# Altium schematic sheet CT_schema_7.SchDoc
size 405 x 220 mm
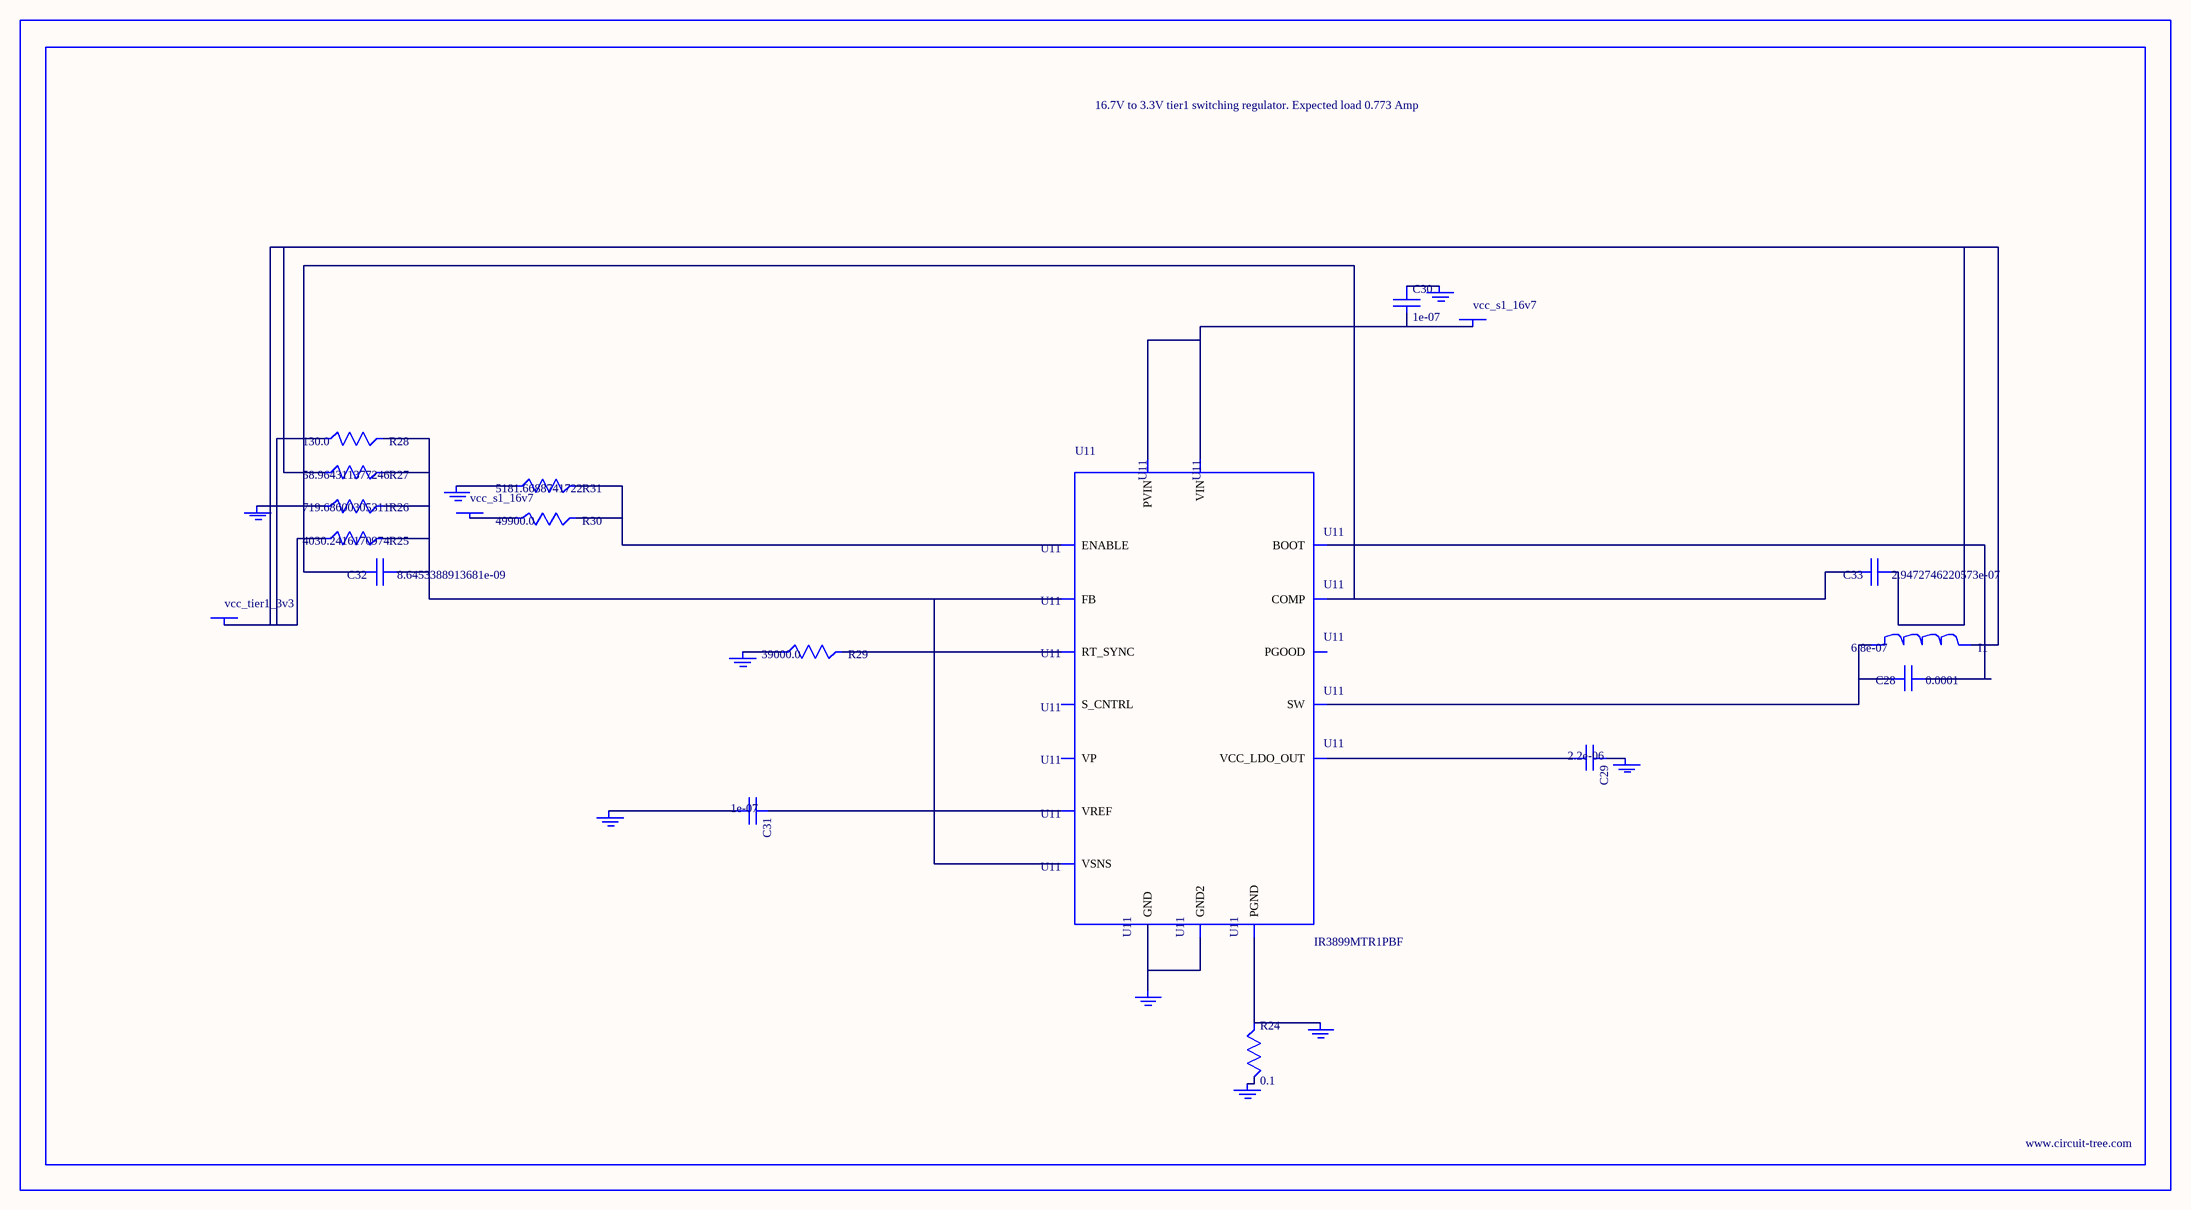
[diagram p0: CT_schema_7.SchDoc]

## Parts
BORDER6  (no value)
C28  0.0001  [C1210]
C29  2.2e-06  [C0603]
C30  1e-07  [C0402]
C31  1e-07  [C0402]
C32  8.6453388913681e-09  [R0603]
C33  2.9472746220573e-07  [R0603]
GND_INSTANCE_6_0  (no value)
GND_INSTANCE_6_1  (no value)
GND_INSTANCE_6_2  (no value)
GND_INSTANCE_6_3  (no value)
GND_INSTANCE_6_4  (no value)
GND_INSTANCE_6_5  (no value)
GND_INSTANCE_6_6  (no value)
GND_INSTANCE_6_7  (no value)
GND_INSTANCE_6_8  (no value)
I1  6.8e-07  [IND25X25CZ]
POWER_INSTANCE_6_0  vcc_s1_16v7
POWER_INSTANCE_6_1  vcc_s1_16v7
POWER_INSTANCE_6_2  vcc_tier1_3v3
R24  0.1  [R0603]
R25  4030.2416170974  [R0603]
R26  719.68600305311  [R0603]
R27  58.964311377246  [R0603]
R28  130.0  [R0603]
R29  39000.0  [R0603]
R30  49900.0  [R0603]
R31  5181.6688741722  [R0603]
U11  IR3899MTR1PBF  [IR3899MTR1PBF]

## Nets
NetC28_1: C28.1 U11.14(BOOT)
NetC28_2: C28.2 I1.1 U11.12(SW)
NetC29_1: C29.1 GND_INSTANCE_6_4.0(GND)
NetC29_2: C29.2 U11.10(VCC_LDO_OUT)
NetC30_1: C30.1 GND_INSTANCE_6_3.0(GND)
NetC30_2: C30.2 POWER_INSTANCE_6_0.0(PWR) U11.9(VIN) U11.13(PVIN)
NetC31_1: C31.1 U11.2(VREF)
NetC31_2: C31.2 GND_INSTANCE_6_1.0(GND)
NetC32_1: C32.1 R25.2 R26.2 R27.2 R28.2 U11.1(FB) U11.8(VSNS)
NetC32_2: C32.2 C33.2 U11.3(COMP)
NetC33_1: C33.1 I1.2 POWER_INSTANCE_6_2.0(PWR) R25.1 R27.1 R28.1
NetGND_INSTANCE_6_0_0: GND_INSTANCE_6_0.0(GND) R26.1
NetGND_INSTANCE_6_2_0: GND_INSTANCE_6_2.0(GND) R29.1
NetGND_INSTANCE_6_5_0: GND_INSTANCE_6_5.0(GND) R24.2
NetGND_INSTANCE_6_6_0: GND_INSTANCE_6_6.0(GND) R24.1 U11.11(PGND)
NetGND_INSTANCE_6_7_0: GND_INSTANCE_6_7.0(GND) R31.1
NetGND_INSTANCE_6_8_0: GND_INSTANCE_6_8.0(GND) U11.4(GND) U11.17(GND2)
NetPOWER_INSTANCE_6_1_0: POWER_INSTANCE_6_1.0(PWR) R30.1
NetR29_2: R29.2 U11.5(RT_SYNC)
NetR30_2: R30.2 R31.2 U11.15(ENABLE)

Not connected (* = marked no-connect by the designer): U11 6(S_CNTRL) 7(PGOOD) 16(VP)

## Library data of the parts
BORDER6 = BORDER_PAGE6
C28 = GRM32ER61A107ME20L
C29 = C0603C225K8RACTU
C30 C31 = C0402C104K3RACTU
C32 = C32
C33 = C33
GND_INSTANCE_6_0-GND_INSTANCE_6_8 = GND
I1 = IHLP2525CZERR68M01
POWER_INSTANCE_6_0-POWER_INSTANCE_6_2 = PWR
R24 = ERJ-3RSFR10V
R25 = R25
R26 = R26
R27 = R27
R28 = RC0603JR-07130RL
R29 = RC0603JR-0739KL
R30 = RC0603FR-0749K9
R31 = R31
